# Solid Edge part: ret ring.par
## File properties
Author: Robert a Rhodes jr
Template: normal.par
Last saved by: Cadcim
Revision: 4
Application: Solid Edge
Density: 0.0000078 kg/mm^3
Accuracy: 0.01
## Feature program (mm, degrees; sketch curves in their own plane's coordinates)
sketch for "unnamed RevolvedProtrusion 1" plane through (0, 25.4, 0) normal (0, -1, 0) x-axis (1, 0, 0)
  line (-42.2288, 1.129) -> (-38.3369, 1.129)
  line (-38.3369, 1.129) -> (-38.3369, 0)
  line (-38.3369, 0) -> (-42.2288, 0)
  line (-42.2288, 0) -> (-42.2288, 1.129)
revolve "unnamed RevolvedProtrusion 1" add finite about sketch line (-42.1776, -8.3958) -> (-20.1067, -8.3958)
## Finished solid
Body 1: solid body, 6 faces, 12 edges, 8 vertices.
  Faces by surface: plane 4, cylinder 2
  Edges by curve: line 8, circle 4
Bounding box of the edges (mm): 3.892 x 19.050 x 18.157, from (-42.2288, 15.8752, -17.0282) to (-38.3369, 34.9248, 1.129).
Cylindrical faces by radius (mm): R8.3958 x1, R9.5248 x1
Planar faces by outward normal: +x 1, -x 1, oblique 2
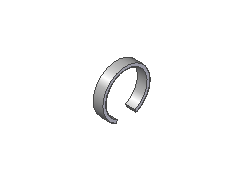
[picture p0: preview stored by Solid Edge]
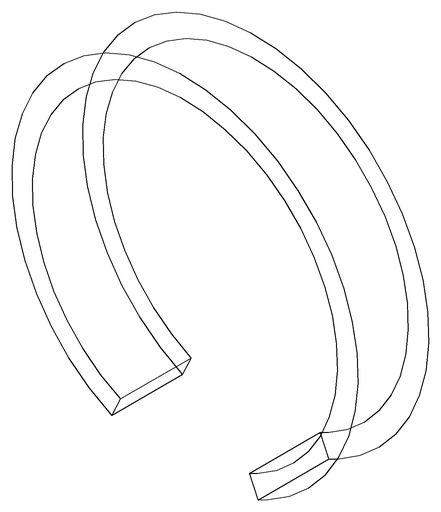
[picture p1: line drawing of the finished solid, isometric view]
